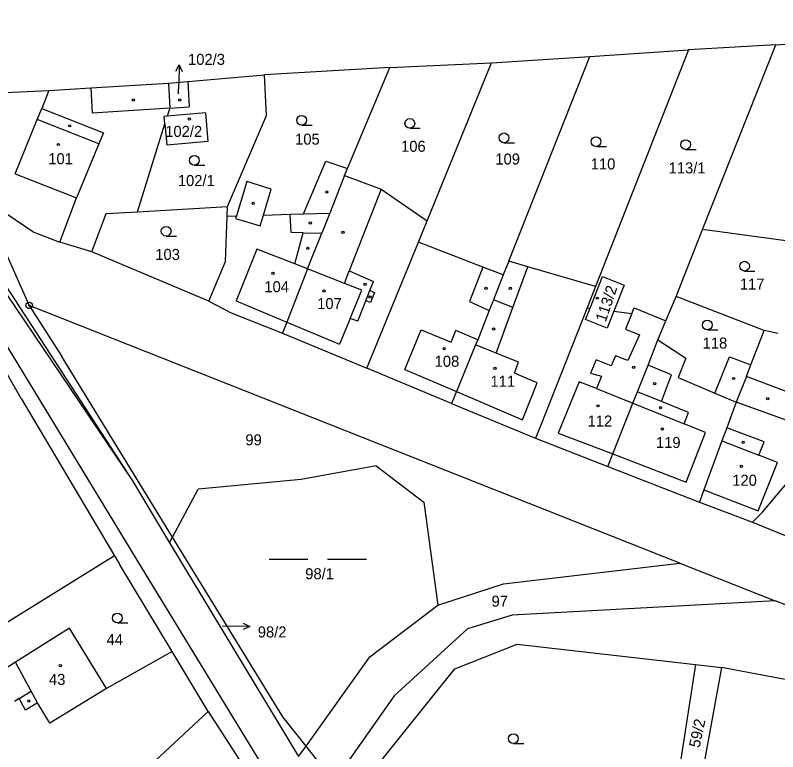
# Model space of a CAD drawing. Extents: x -762263 to -760336, y -1154405 to -1152076.
# Drawn here: x -761696.3 to -761578.9, y -1152351.2 to -1152237.6 of the extents above; entities that cross this region are included whole.
import ezdxf

# ---------------------------------------------------------------- set-up
doc = ezdxf.new("R2010")
doc.units = 0
for name, color, linetype in [('Vrstva 1', 7, 'Continuous'), ('Vrstva 16', 7, 'Continuous'), ('Vrstva 18', 7, 'Continuous'), ('Vrstva 19', 7, 'Continuous'), ('Vrstva 24', 7, 'Continuous'), ('Vrstva 25', 7, 'Continuous'), ('Vrstva 4', 7, 'Continuous')]:
    doc.layers.add(name, color=color, linetype=linetype)

msp = doc.modelspace()

# ---------------------------------------------------------------- linework, layer by layer
at = {"layer": 'Vrstva 1'}
for p, q in [((-761724.89, -1152237.64), (-761678.25, -1152309.43)), ((-761579.13, -1152242.2), (-761531.66, -1152238.76)), ((-761579.13, -1152242.2), (-761592.6, -1152242.98)), ((-761590.44, -1152270.65), (-761579.13, -1152242.2)), ((-761622.93, -1152244.98), (-761607.81, -1152243.98)), ((-761620.28, -1152275.53), (-761607.81, -1152243.98)), ((-761607.81, -1152243.98), (-761592.6, -1152242.98)), ((-761592.6, -1152242.98), (-761606.95, -1152279.46)), ((-761638.61, -1152245.7), (-761622.93, -1152244.98)), ((-761632.87, -1152269.33), (-761622.93, -1152244.98)), ((-761638.61, -1152245.7), (-761657.91, -1152246.82)), ((-761645.14, -1152261.28), (-761638.61, -1152245.7)), ((-761669.71, -1152247.83), (-761657.91, -1152246.82)), ((-761657.59, -1152253.07), (-761657.91, -1152246.82)), ((-761684.68, -1152248.84), (-761672.7, -1152248.09)), ((-761672.7, -1152248.09), (-761669.71, -1152247.83)), ((-761672.7, -1152248.09), (-761672.52, -1152251.95)), ((-761669.71, -1152247.83), (-761669.54, -1152251.75)), ((-761713.2, -1152250.29), (-761691.15, -1152249.25)), ((-761691.15, -1152249.25), (-761692.22, -1152252.03)), ((-761691.15, -1152249.25), (-761684.68, -1152248.84)), ((-761692.94, -1152253.71), (-761692.22, -1152252.03)), ((-761672.52, -1152251.95), (-761672.9, -1152253.19)), ((-761672.52, -1152251.95), (-761669.54, -1152251.75)), ((-761672.9, -1152253.19), (-761673.37, -1152253.23)), ((-761673.27, -1152254.37), (-761673.37, -1152253.23)), ((-761667.03, -1152252.67), (-761672.9, -1152253.19)), ((-761667.03, -1152252.67), (-761666.64, -1152257.09)), ((-761663.6, -1152267.11), (-761657.59, -1152253.07)), ((-761696.31, -1152262.08), (-761692.94, -1152253.71)), ((-761677.47, -1152267.93), (-761673.27, -1152254.37)), ((-761673.27, -1152254.37), (-761672.98, -1152257.65)), ((-761666.64, -1152257.09), (-761672.98, -1152257.65)), ((-761651.93, -1152268.26), (-761648.49, -1152260.11)), ((-761648.49, -1152260.11), (-761645.14, -1152261.28)), ((-761645.58, -1152262.34), (-761645.14, -1152261.28)), ((-761696.31, -1152262.08), (-761686.89, -1152265.81)), ((-761645.58, -1152262.34), (-761647.87, -1152268.14)), ((-761645.58, -1152262.34), (-761639.95, -1152264.45)), ((-761660.65, -1152263.29), (-761662.25, -1152268.56)), ((-761656.87, -1152264.45), (-761660.65, -1152263.29)), ((-761658.09, -1152268.44), (-761656.87, -1152264.45)), ((-761639.95, -1152264.45), (-761632.87, -1152269.33)), ((-761701.68, -1152265.53), (-761693.47, -1152271.1)), ((-761701.68, -1152265.53), (-761694.17, -1152282.36)), ((-761689.44, -1152272.64), (-761686.89, -1152265.81)), ((-761677.47, -1152267.93), (-761663.6, -1152267.11)), ((-761663.66, -1152268.6), (-761663.6, -1152267.11)), ((-761684.52, -1152274.1), (-761682.29, -1152268.22)), ((-761682.29, -1152268.22), (-761677.47, -1152267.93)), ((-761663.93, -1152275.58), (-761663.66, -1152268.6)), ((-761663.66, -1152268.6), (-761662.25, -1152268.56)), ((-761658.09, -1152268.44), (-761653.95, -1152268.32)), ((-761653.95, -1152268.32), (-761651.93, -1152268.26)), ((-761647.87, -1152268.14), (-761649.09, -1152271.25)), ((-761634.21, -1152272.62), (-761632.87, -1152269.33)), ((-761594.5, -1152281.01), (-761590.44, -1152270.65)), ((-761574.61, -1152272.81), (-761590.44, -1152270.65)), ((-761693.47, -1152271.1), (-761689.44, -1152272.64)), ((-761651.27, -1152276.75), (-761649.09, -1152271.25)), ((-761684.52, -1152274.1), (-761689.44, -1152272.64)), ((-761642.13, -1152292.02), (-761634.21, -1152272.62)), ((-761624.29, -1152276.45), (-761634.21, -1152272.62)), ((-761666.48, -1152281.73), (-761684.52, -1152274.1)), ((-761666.48, -1152281.73), (-761663.93, -1152275.58)), ((-761620.28, -1152275.53), (-761621.13, -1152277.67)), ((-761617.33, -1152276.4), (-761620.28, -1152275.53)), ((-761651.27, -1152276.75), (-761654.49, -1152284.93)), ((-761621.13, -1152277.67), (-761624.29, -1152276.45)), ((-761606.95, -1152279.46), (-761617.33, -1152276.4)), ((-761621.13, -1152277.67), (-761622.65, -1152281.52)), ((-761607.75, -1152282.78), (-761605.84, -1152277.92)), ((-761605.84, -1152277.92), (-761602.53, -1152279.26)), ((-761606.95, -1152279.46), (-761608.23, -1152282.72)), ((-761602.53, -1152279.26), (-761604.1, -1152283.25)), ((-761622.65, -1152281.52), (-761623.29, -1152283.14)), ((-761596.08, -1152284.74), (-761594.5, -1152281.01)), ((-761580.96, -1152286.22), (-761594.5, -1152281.01)), ((-761694.17, -1152282.36), (-761689.16, -1152290.23)), ((-761593.96, -1152322.08), (-761694.17, -1152282.36)), ((-761666.48, -1152281.73), (-761663.03, -1152283.5)), ((-761608.23, -1152282.72), (-761615.46, -1152301.08)), ((-761608.23, -1152282.72), (-761607.75, -1152282.78)), ((-761663.03, -1152283.5), (-761655.17, -1152286.65)), ((-761623.29, -1152283.14), (-761625.05, -1152287.66)), ((-761608.45, -1152284.54), (-761607.75, -1152282.78)), ((-761604.1, -1152283.25), (-761605.12, -1152285.87)), ((-761604.1, -1152283.25), (-761601.33, -1152283.61)), ((-761601.33, -1152283.61), (-761600.98, -1152282.75)), ((-761600.98, -1152282.75), (-761596.08, -1152284.74)), ((-761654.49, -1152284.93), (-761655.17, -1152286.65)), ((-761605.12, -1152285.87), (-761608.45, -1152284.54)), ((-761597.31, -1152287.66), (-761596.08, -1152284.74)), ((-761582.98, -1152291.54), (-761580.96, -1152286.22)), ((-761578.82, -1152286.7), (-761580.96, -1152286.22)), ((-761655.17, -1152286.65), (-761642.13, -1152292.02)), ((-761625.39, -1152288.47), (-761628.35, -1152295.65)), ((-761625.05, -1152287.66), (-761625.39, -1152288.47)), ((-761598.84, -1152291.57), (-761597.31, -1152287.66)), ((-761597.31, -1152287.66), (-761593, -1152290.52)), ((-761695.4, -1152296.7), (-761698.99, -1152290.5)), ((-761672.07, -1152318.08), (-761689.16, -1152290.23)), ((-761593, -1152290.52), (-761594.19, -1152293.5)), ((-761588.54, -1152295.9), (-761586.28, -1152290.29)), ((-761586.28, -1152290.29), (-761582.98, -1152291.54)), ((-761629.09, -1152297.47), (-761642.13, -1152292.02)), ((-761600.48, -1152295.7), (-761598.84, -1152291.57)), ((-761583.66, -1152293.33), (-761582.98, -1152291.54)), ((-761594.19, -1152293.5), (-761588.54, -1152295.9)), ((-761583.66, -1152293.33), (-761585.26, -1152297.27)), ((-761576.06, -1152296.21), (-761583.66, -1152293.33)), ((-761628.35, -1152295.65), (-761629.09, -1152297.47)), ((-761695.4, -1152296.7), (-761681.01, -1152320.98)), ((-761601.17, -1152297.43), (-761600.48, -1152295.7)), ((-761629.09, -1152297.47), (-761616.15, -1152302.85)), ((-761604.28, -1152305.26), (-761601.17, -1152297.43)), ((-761585.26, -1152297.27), (-761586.68, -1152301.22)), ((-761615.46, -1152301.08), (-761616.15, -1152302.85)), ((-761586.68, -1152301.22), (-761587.45, -1152303.24)), ((-761616.15, -1152302.85), (-761605.02, -1152307.18)), ((-761587.45, -1152303.24), (-761590.23, -1152310.8)), ((-761581.18, -1152314.22), (-761572.66, -1152304.01)), ((-761605.02, -1152307.18), (-761604.28, -1152305.26)), ((-761640.73, -1152307.11), (-761652.28, -1152309.21)), ((-761640.73, -1152307.11), (-761633.37, -1152312.7)), ((-761605.02, -1152307.18), (-761590.9, -1152312.7)), ((-761678.25, -1152309.43), (-761672.53, -1152318.94)), ((-761652.28, -1152309.21), (-761668.16, -1152310.71)), ((-761672.07, -1152318.08), (-761668.16, -1152310.71)), ((-761590.23, -1152310.8), (-761590.9, -1152312.7)), ((-761633.37, -1152312.7), (-761631.23, -1152328.56)), ((-761590.9, -1152312.7), (-761582.72, -1152315.79)), ((-761582.72, -1152315.79), (-761581.18, -1152314.22)), ((-761582.72, -1152315.79), (-761574.99, -1152318.93)), ((-761672.53, -1152318.94), (-761672.07, -1152318.08)), ((-761672.53, -1152318.94), (-761652.68, -1152351.91)), ((-761655.09, -1152345.77), (-761672.07, -1152318.08)), ((-761681.01, -1152320.98), (-761705.66, -1152336.28)), ((-761681.01, -1152320.98), (-761680.26, -1152322.24)), ((-761672.13, -1152335.74), (-761680.26, -1152322.24)), ((-761621.09, -1152325.31), (-761593.96, -1152322.08)), ((-761593.96, -1152322.08), (-761579.27, -1152327.9)), ((-761631.23, -1152328.56), (-761621.09, -1152325.31)), ((-761579.27, -1152327.9), (-761619.79, -1152330.11)), ((-761556.18, -1152337.06), (-761579.27, -1152327.9)), ((-761641.67, -1152336.56), (-761631.23, -1152328.56)), ((-761619.79, -1152330.11), (-761626.64, -1152332.22)), ((-761687.95, -1152332.14), (-761696.26, -1152337.36)), ((-761682.26, -1152341.41), (-761687.95, -1152332.14)), ((-761626.64, -1152332.22), (-761637.94, -1152342.53)), ((-761628.6, -1152338.37), (-761618.98, -1152334.56)), ((-761618.98, -1152334.56), (-761591.52, -1152337.7)), ((-761672.13, -1152335.74), (-761682.26, -1152341.41)), ((-761666.57, -1152344.96), (-761672.13, -1152335.74)), ((-761651.52, -1152350.29), (-761641.67, -1152336.56)), ((-761696.26, -1152337.36), (-761699.1, -1152339.15)), ((-761591.52, -1152337.7), (-761594.93, -1152359.73)), ((-761591.52, -1152337.7), (-761587.54, -1152338.16)), ((-761642.77, -1152356.08), (-761628.6, -1152338.37)), ((-761587.54, -1152338.16), (-761591.19, -1152358.32)), ((-761556.79, -1152344.07), (-761587.54, -1152338.16)), ((-761637.94, -1152342.53), (-761647.23, -1152355.71)), ((-761666.57, -1152344.96), (-761693.55, -1152370)), ((-761666.57, -1152344.96), (-761658.76, -1152357.09)), ((-761651.52, -1152350.29), (-761655.09, -1152345.77)), ((-761652.68, -1152351.91), (-761651.52, -1152350.29)), ((-761647.23, -1152355.71), (-761651.52, -1152350.29))]:
    msp.add_line(p, q, dxfattribs=at)
at = {"layer": 'Vrstva 16'}
for p, q in [((-761671.086, -1152245.29), (-761671.12, -1152248.29)), ((-761671.14, -1152249.78), (-761671.12, -1152248.29)), ((-761664.4, -1152331.78), (-761663.19, -1152331.8)), ((-761660.19, -1152331.849), (-761663.19, -1152331.8))]:
    msp.add_line(p, q, dxfattribs=at)
for points in [[(-761671.598, -1152246.285), (-761671.086, -1152245.29), (-761670.598, -1152246.296)], [(-761661.182, -1152331.333), (-761660.19, -1152331.849), (-761661.198, -1152332.333)]]:
    msp.add_lwpolyline(points, dxfattribs=at)
at = {"layer": 'Vrstva 24'}
for radius in [0.5, 0.1]:
    msp.add_circle((-761694.17, -1152282.36), radius, dxfattribs=at)
at = {"layer": 'Vrstva 25'}
for p, q in [((-761652.18, -1152254.58), (-761650.58, -1152254.58)), ((-761635.53, -1152255.07), (-761633.93, -1152255.07)), ((-761621.03, -1152257.29), (-761619.43, -1152257.29)), ((-761606.84, -1152257.87), (-761605.24, -1152257.87)), ((-761593.04, -1152258.32), (-761591.44, -1152258.32)), ((-761668.72, -1152260.77), (-761667.12, -1152260.77)), ((-761673.07, -1152271.68), (-761671.47, -1152271.68)), ((-761583.97, -1152277.07), (-761582.37, -1152277.07)), ((-761589.69, -1152286.15), (-761588.09, -1152286.15)), ((-761657.22, -1152321.47), (-761651.22, -1152321.47)), ((-761648.22, -1152321.47), (-761642.22, -1152321.47)), ((-761680.58, -1152331.31), (-761678.98, -1152331.31)), ((-761619.57, -1152349.89), (-761617.97, -1152349.89))]:
    msp.add_line(p, q, dxfattribs=at)
for centre, radius in [((-761678.11, -1152250.72), 0.175), ((-761670.97, -1152250.7), 0.175), ((-761652.18, -1152253.83), 0.75), ((-761687.91, -1152254.69), 0.175), ((-761669.51, -1152253.64), 0.175), ((-761635.53, -1152254.32), 0.75), ((-761621.03, -1152256.54), 0.75), ((-761606.84, -1152257.12), 0.75), ((-761593.04, -1152257.57), 0.75), ((-761689.68, -1152257.56), 0.175), ((-761668.72, -1152260.02), 0.75), ((-761648.32, -1152264.88), 0.175), ((-761659.66, -1152266.63), 0.175), ((-761650.84, -1152269.66), 0.175), ((-761673.07, -1152270.93), 0.75), ((-761645.82, -1152271.12), 0.175), ((-761651.24, -1152273.57), 0.175), ((-761583.97, -1152276.32), 0.75), ((-761656.61, -1152277.42), 0.175), ((-761642.44, -1152279.13), 0.175), ((-761648.74, -1152280.16), 0.175), ((-761623.8, -1152279.73), 0.175), ((-761620.03, -1152279.73), 0.175), ((-761641.66, -1152281.09), 0.175), ((-761606.66, -1152281.25), 0.175), ((-761589.69, -1152285.4), 0.75), ((-761622.62, -1152286.02), 0.175), ((-761630.24, -1152289.02), 0.175), ((-761622.43, -1152292.05), 0.175), ((-761601.03, -1152291.92), 0.175), ((-761597.82, -1152294.41), 0.175), ((-761585.66, -1152293.63), 0.175), ((-761580.4, -1152296.75), 0.175), ((-761606.55, -1152297.85), 0.175), ((-761596.92, -1152298.11), 0.175), ((-761596.63, -1152301.4), 0.175), ((-761584.18, -1152303.49), 0.175), ((-761584.48, -1152307.19), 0.175), ((-761680.58, -1152330.56), 0.75), ((-761689.36, -1152337.91), 0.175), ((-761694.22, -1152343.33), 0.175), ((-761619.57, -1152349.14), 0.75)]:
    msp.add_circle(centre, radius, dxfattribs=at)
at = {"layer": 'Vrstva 4'}
for p, q in [((-761684.68, -1152248.84), (-761684.46, -1152252.74)), ((-761717.85, -1152250.76), (-761678.25, -1152309.43)), ((-761692.22, -1152252.03), (-761682.74, -1152255.75)), ((-761672.52, -1152251.95), (-761684.46, -1152252.74)), ((-761683.44, -1152257.46), (-761692.94, -1152253.71)), ((-761682.74, -1152255.75), (-761683.44, -1152257.46)), ((-761683.44, -1152257.46), (-761686.89, -1152265.81)), ((-761639.95, -1152264.45), (-761644.85, -1152277.05)), ((-761662.25, -1152268.56), (-761662.37, -1152268.97)), ((-761658.6, -1152270.12), (-761658.09, -1152268.44)), ((-761653.79, -1152271.12), (-761653.95, -1152268.32)), ((-761651.93, -1152268.26), (-761647.87, -1152268.14)), ((-761662.37, -1152268.97), (-761658.6, -1152270.12)), ((-761651.94, -1152271.17), (-761653.79, -1152271.12)), ((-761653.27, -1152275.97), (-761651.94, -1152271.17)), ((-761651.94, -1152271.17), (-761649.09, -1152271.25)), ((-761659.1, -1152273.69), (-761662.3, -1152281.66)), ((-761653.27, -1152275.97), (-761659.1, -1152273.69)), ((-761651.27, -1152276.75), (-761653.27, -1152275.97)), ((-761645.6, -1152278.97), (-761651.27, -1152276.75)), ((-761624.29, -1152276.45), (-761626.35, -1152281.76)), ((-761619.65, -1152282.7), (-761617.33, -1152276.4)), ((-761676.88, -1152322.72), (-761704.32, -1152277.54)), ((-761645.6, -1152278.97), (-761644.85, -1152277.05)), ((-761644.85, -1152277.05), (-761641.11, -1152278.69)), ((-761642.92, -1152280.02), (-761645.6, -1152278.97)), ((-761641.67, -1152280.08), (-761641.11, -1152278.69)), ((-761644.74, -1152284.38), (-761642.92, -1152280.02)), ((-761642.3, -1152281.66), (-761641.67, -1152280.08)), ((-761641.67, -1152280.08), (-761640.97, -1152280.36)), ((-761640.97, -1152280.36), (-761641.6, -1152281.94)), ((-761619.65, -1152282.7), (-761622.65, -1152281.52)), ((-761662.3, -1152281.66), (-761654.49, -1152284.93)), ((-761643.56, -1152284.81), (-761642.3, -1152281.66)), ((-761641.6, -1152281.94), (-761642.3, -1152281.66)), ((-761626.35, -1152281.76), (-761623.29, -1152283.14)), ((-761622.24, -1152289.74), (-761619.65, -1152282.7)), ((-761601.33, -1152283.61), (-761602.3, -1152286.02)), ((-761654.49, -1152284.93), (-761646.38, -1152288.32)), ((-761644.74, -1152284.38), (-761646.38, -1152288.32)), ((-761643.56, -1152284.81), (-761644.74, -1152284.38)), ((-761636.3, -1152292.26), (-761633.8, -1152286.12)), ((-761633.8, -1152286.12), (-761629.14, -1152288.02)), ((-761629.14, -1152288.02), (-761628.45, -1152286.21)), ((-761625.05, -1152287.66), (-761628.45, -1152286.21)), ((-761602.3, -1152286.02), (-761600.15, -1152286.89)), ((-761600.15, -1152286.89), (-761601.95, -1152290.87)), ((-761622.24, -1152289.74), (-761625.39, -1152288.47)), ((-761618.81, -1152291.12), (-761622.24, -1152289.74)), ((-761606.84, -1152290.77), (-761607.69, -1152292.79)), ((-761604.52, -1152291.69), (-761606.84, -1152290.77)), ((-761603.87, -1152290.14), (-761604.52, -1152291.69)), ((-761601.95, -1152290.87), (-761603.87, -1152290.14)), ((-761619.41, -1152292.81), (-761618.81, -1152291.12)), ((-761595.22, -1152293.05), (-761598.84, -1152291.57)), ((-761636.3, -1152292.26), (-761628.35, -1152295.65)), ((-761615.94, -1152294.31), (-761619.41, -1152292.81)), ((-761607.69, -1152292.79), (-761606.01, -1152293.28)), ((-761606.01, -1152293.28), (-761606.77, -1152295.16)), ((-761596.74, -1152297.2), (-761595.22, -1152293.05)), ((-761618.18, -1152299.98), (-761615.94, -1152294.31)), ((-761609.47, -1152294.13), (-761612.69, -1152302.04)), ((-761606.77, -1152295.16), (-761609.47, -1152294.13)), ((-761628.35, -1152295.65), (-761618.18, -1152299.98)), ((-761606.77, -1152295.16), (-761601.17, -1152297.43)), ((-761596.74, -1152297.2), (-761600.48, -1152295.7)), ((-761588.54, -1152295.9), (-761585.26, -1152297.27)), ((-761601.17, -1152297.43), (-761593.28, -1152300.62)), ((-761592.61, -1152298.85), (-761596.74, -1152297.2)), ((-761577.57, -1152300.05), (-761585.26, -1152297.27)), ((-761593.28, -1152300.62), (-761592.61, -1152298.85)), ((-761589.96, -1152301.96), (-761593.28, -1152300.62)), ((-761580.96, -1152303.4), (-761586.68, -1152301.22)), ((-761612.69, -1152302.04), (-761604.28, -1152305.26)), ((-761592.94, -1152309.61), (-761589.96, -1152301.96)), ((-761587.45, -1152303.24), (-761581.78, -1152305.45)), ((-761581.78, -1152305.45), (-761580.96, -1152303.4)), ((-761604.28, -1152305.26), (-761592.94, -1152309.61)), ((-761578.89, -1152306.58), (-761581.78, -1152305.45)), ((-761581.85, -1152314.05), (-761578.89, -1152306.58)), ((-761590.23, -1152310.8), (-761581.85, -1152314.05)), ((-761655.41, -1152357.82), (-761676.88, -1152322.72)), ((-761693.85, -1152341.82), (-761696.26, -1152337.36)), ((-761682.26, -1152341.41), (-761690.98, -1152346.74)), ((-761695.69, -1152342.97), (-761693.85, -1152341.82)), ((-761692.88, -1152343.63), (-761693.85, -1152341.82)), ((-761695.69, -1152342.97), (-761696.41, -1152343.42)), ((-761694.74, -1152344.77), (-761695.69, -1152342.97)), ((-761692.88, -1152343.63), (-761694.74, -1152344.77)), ((-761690.98, -1152346.74), (-761692.88, -1152343.63))]:
    msp.add_line(p, q, dxfattribs=at)

# ---------------------------------------------------------------- texts
at = {"layer": 'Vrstva 16'}
for s, p in [('102/3', (-761669.697, -1152245.29)), ('98/2', (-761658.953, -1152333.55))]:
    msp.add_text(s, height=1.7, dxfattribs=at).set_placement(p)
at = {"layer": 'Vrstva 18'}
for s, height, p in [('105', 1.7, (-761653.207, -1152257.59)), ('106', 1.7, (-761636.877, -1152258.69)), ('109', 1.7, (-761622.357, -1152260.65)), ('110', 1.7, (-761607.657, -1152261.41)), ('113/1', 1.7, (-761595.666, -1152262.02)), ('102/1', 1.7, (-761671.268, -1152263.97)), ('103', 1.7, (-761674.74, -1152275.36)), ('117', 1.7, (-761584.697, -1152279.93)), ('118', 1.7, (-761590.427, -1152289.02)), ('99', 1.7, (-761660.863, -1152303.94)), ('98/1', 1.7, (-761651.643, -1152324.58)), ('97', 1.7, (-761622.943, -1152328.81)), ('98/2', 0.1, (-761664.567, -1152331.78)), ('44', 1.7, (-761682.245, -1152334.72))]:
    msp.add_text(s, height=height, dxfattribs=at).set_placement(p)
msp.add_text('59/2', height=1.7, rotation=78.03685, dxfattribs=at).set_placement((-761590.894, -1152350.642))
at = {"layer": 'Vrstva 19'}
for s, height, p in [('102/3', 0.1, (-761671.333, -1152249.78)), ('102/2', 1.7, (-761673.209, -1152256.39)), ('101', 1.7, (-761691.225, -1152260.6)), ('104', 1.7, (-761657.937, -1152280.33)), ('107', 1.7, (-761649.807, -1152282.93)), ('108', 1.7, (-761631.707, -1152291.83)), ('111', 1.7, (-761623.107, -1152294.91)), ('112', 1.7, (-761608.152, -1152301.04)), ('119', 1.7, (-761597.617, -1152304.35)), ('120', 1.7, (-761585.867, -1152310.17)), ('43', 1.7, (-761691.112, -1152340.86))]:
    msp.add_text(s, height=height, dxfattribs=at).set_placement(p)
msp.add_text('113/2', height=1.7, rotation=71.39054, dxfattribs=at).set_placement((-761605.365, -1152285.046))

doc.saveas('drawing.dxf')
